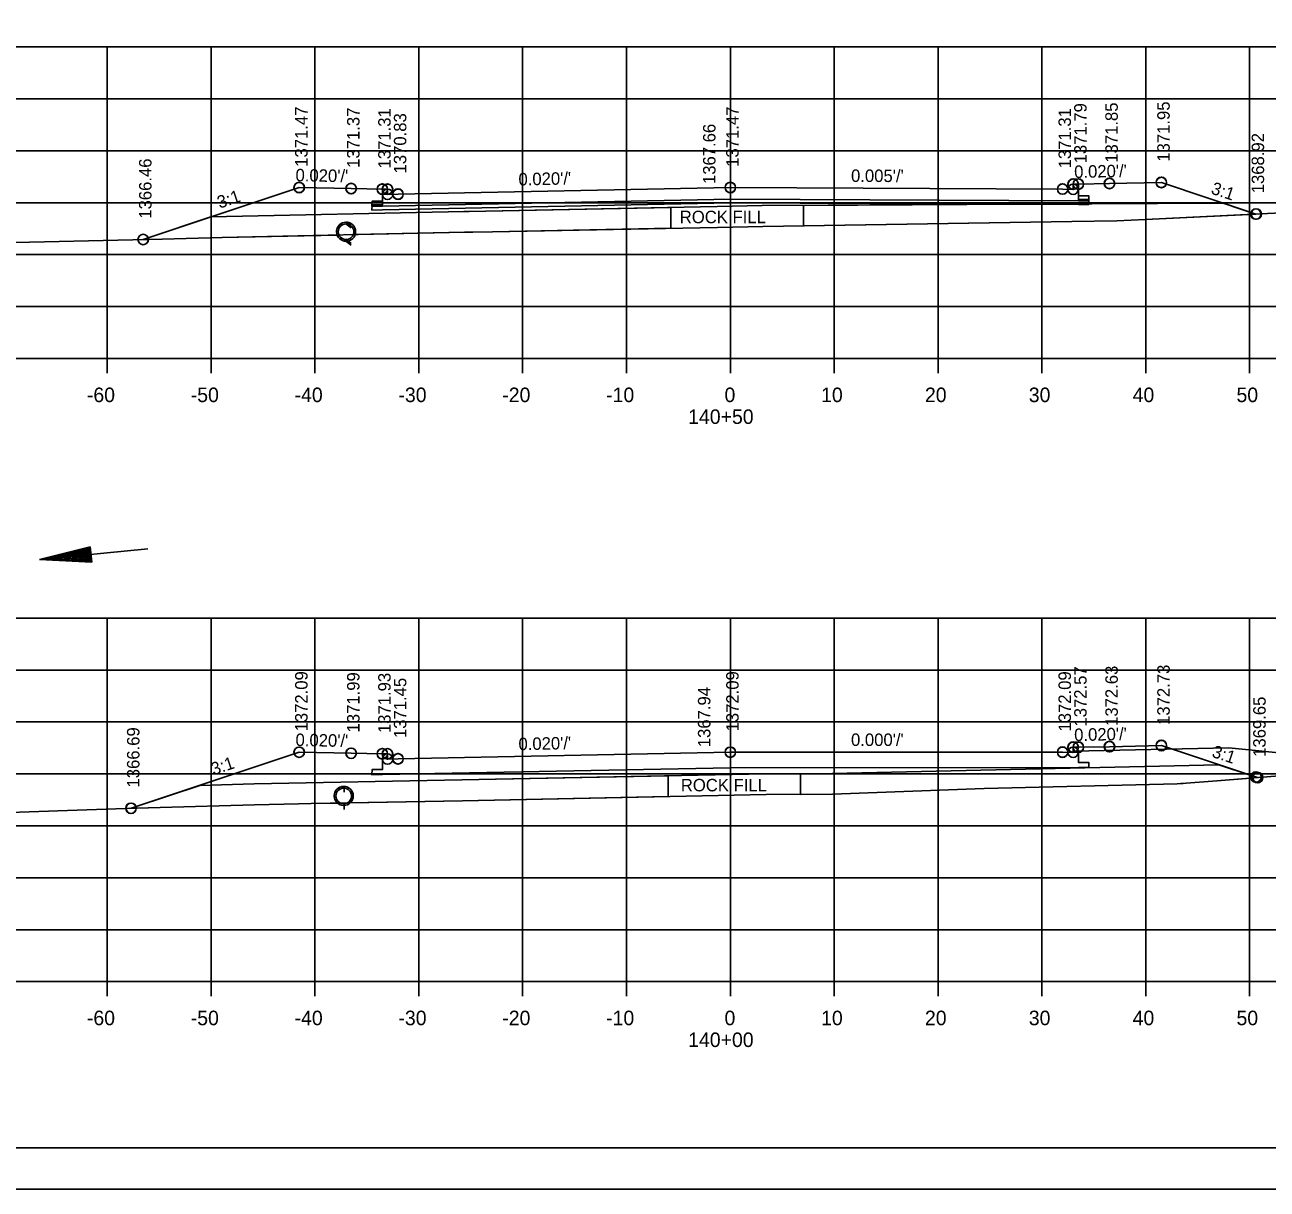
# Model space of a CAD drawing. Extents: x 1374311 to 1383814, y 384102 to 406278.
# Drawn here: x 1381560.7 to 1381680.4, y 389231.4 to 389343.5 of the extents above; entities that cross this region are included whole.
import ezdxf

# ---------------------------------------------------------------- set-up
doc = ezdxf.new("R2010")
doc.units = 0
for name, color, linetype in [('R_Axis', 7, 'Continuous'), ('R_Axis Annot', 7, 'Continuous'), ('R_Border', 7, 'Continuous'), ('R_Draft', 7, 'Continuous'), ('R_Exist Surface', 7, 'Continuous'), ('R_Fin Surface', 7, 'Continuous'), ('R_Grid', 7, 'Continuous'), ('R_No Plot', 7, 'Continuous'), ('R_Water', 7, 'Continuous'), ('R_Xsect Elev', 7, 'Continuous'), ('R_Xsect Slope', 7, 'Continuous')]:
    doc.layers.add(name, color=color, linetype=linetype)

msp = doc.modelspace()

# ---------------------------------------------------------------- linework, layer by layer
at = {"layer": 'R_Axis'}
for p, q in [((1381488.66, 389311.36), (1381768.66, 389311.36)), ((1381568.66, 389309.96), (1381568.66, 389311.36)), ((1381578.66, 389309.96), (1381578.66, 389311.36)), ((1381588.66, 389309.96), (1381588.66, 389311.36)), ((1381598.66, 389309.96), (1381598.66, 389311.36)), ((1381608.66, 389309.96), (1381608.66, 389311.36)), ((1381618.66, 389309.96), (1381618.66, 389311.36)), ((1381628.66, 389309.96), (1381628.66, 389311.36)), ((1381638.66, 389309.96), (1381638.66, 389311.36)), ((1381648.66, 389309.96), (1381648.66, 389311.36)), ((1381658.66, 389309.96), (1381658.66, 389311.36)), ((1381668.66, 389309.96), (1381668.66, 389311.36)), ((1381678.66, 389309.96), (1381678.66, 389311.36)), ((1381488.66, 389251.36), (1381768.66, 389251.36)), ((1381568.66, 389249.96), (1381568.66, 389251.36)), ((1381578.66, 389249.96), (1381578.66, 389251.36)), ((1381588.66, 389249.96), (1381588.66, 389251.36)), ((1381598.66, 389249.96), (1381598.66, 389251.36)), ((1381608.66, 389249.96), (1381608.66, 389251.36)), ((1381618.66, 389249.96), (1381618.66, 389251.36)), ((1381628.66, 389249.96), (1381628.66, 389251.36)), ((1381638.66, 389249.96), (1381638.66, 389251.36)), ((1381648.66, 389249.96), (1381648.66, 389251.36)), ((1381658.66, 389249.96), (1381658.66, 389251.36)), ((1381668.66, 389249.96), (1381668.66, 389251.36)), ((1381678.66, 389249.96), (1381678.66, 389251.36))]:
    msp.add_line(p, q, dxfattribs=at)
at = {"layer": 'R_Border'}
msp.add_line((1381786.84, 389235.36), (1381470.66, 389235.36), dxfattribs=at)
at = {"layer": 'R_Draft'}
for p, q in [((1381567.02, 389293.24), (1381562.12, 389292)), ((1381567.03, 389293.11), (1381562.95, 389292.08)), ((1381567.02, 389293.24), (1381567.17, 389291.74)), ((1381567.17, 389291.74), (1381562.12, 389292)), ((1381567.16, 389291.87), (1381562.95, 389292.08)), ((1381567.05, 389292.98), (1381563.81, 389292.16)), ((1381567.15, 389291.99), (1381563.81, 389292.16)), ((1381567.06, 389292.86), (1381564.64, 389292.25)), ((1381567.13, 389292.12), (1381564.64, 389292.25)), ((1381567.07, 389292.73), (1381565.48, 389292.33)), ((1381567.12, 389292.25), (1381565.48, 389292.33)), ((1381567.08, 389292.61), (1381566.31, 389292.41)), ((1381567.11, 389292.37), (1381566.31, 389292.41)), ((1381661.66, 389273.56), (1381676.65, 389273.86)), ((1381676.65, 389273.86), (1381696.57, 389271.87))]:
    msp.add_line(p, q, dxfattribs=at)
at = {"layer": 'R_Exist Surface'}
for p, q in [((1381591.63, 389324.5), (1381592.15, 389324.11)), ((1381591.63, 389322.67), (1381592.15, 389322.28)), ((1381591.46, 389270.16), (1381591.46, 389269.76)), ((1381591.46, 389268.32), (1381591.46, 389267.93))]:
    msp.add_line(p, q, dxfattribs=at)
for points in [[(1381488.66, 389321.48), (1381496.89, 389321.62), (1381498.05, 389321.64), (1381512.37, 389321.88), (1381515.13, 389321.94), (1381526.33, 389322.13), (1381531.42, 389322.19), (1381541.07, 389322.34), (1381549.06, 389322.42), (1381558.32, 389322.5), (1381573.96, 389322.86), (1381579.74, 389323.01), (1381603.06, 389323.52), (1381603.56, 389323.53), (1381603.85, 389323.54), (1381605.77, 389323.57), (1381627.42, 389323.99), (1381631.78, 389324.08), (1381661.54, 389324.55), (1381665.88, 389324.62), (1381668.65, 389324.75), (1381690.85, 389325.85)], [(1381556.47, 389267.54), (1381570.42, 389268.03), (1381573.75, 389268.14), (1381582.84, 389268.39), (1381587.07, 389268.48), (1381588.3, 389268.5), (1381602.86, 389268.78), (1381632.1, 389269.37), (1381638.51, 389269.4), (1381653.09, 389269.94), (1381671.69, 389270.41), (1381672.03, 389270.42), (1381672.28, 389270.44), (1381672.54, 389270.46), (1381675.08, 389270.65), (1381689.96, 389271.85)]]:
    msp.add_lwpolyline(points, dxfattribs=at)
for centre in [(1381591.66, 389323.57), (1381591.43, 389269.24)]:
    msp.add_circle(centre, 0.917, dxfattribs=at)
at = {"layer": 'R_Fin Surface'}
for p, q in [((1381622.94, 389325.9), (1381622.94, 389323.9)), ((1381622.94, 389323.9), (1381622.94, 389325.9)), ((1381656.66, 389326.21), (1381635.69, 389326.1)), ((1381635.69, 389326.1), (1381635.69, 389324.14)), ((1381635.69, 389326.1), (1381635.69, 389324.14)), ((1381676.14, 389326.31), (1381663.17, 389326.24)), ((1381679.26, 389325.27), (1381676.14, 389326.31)), ((1381578.64, 389324.99), (1381572.6, 389322.98)), ((1381635.69, 389324.14), (1381661.54, 389324.55)), ((1381579.74, 389323.01), (1381590.8, 389323.25)), ((1381603.56, 389323.53), (1381603.85, 389323.54)), ((1381678.8, 389271.21), (1381675.69, 389272.24)), ((1381622.66, 389271.18), (1381622.66, 389269.18)), ((1381622.66, 389269.18), (1381622.66, 389271.18)), ((1381635.42, 389271.38), (1381635.42, 389269.38)), ((1381635.42, 389271.38), (1381635.42, 389269.38)), ((1381577.56, 389270.25), (1381571.43, 389268.21)), ((1381591.46, 389270.16), (1381591.46, 389270.15))]:
    msp.add_line(p, q, dxfattribs=at)
for points in [[(1381572.12, 389322.82), (1381587.15, 389327.82), (1381592.15, 389327.72), (1381595.15, 389327.66), (1381595.65, 389327.66), (1381595.66, 389327.16), (1381596.66, 389327.18), (1381628.66, 389327.82), (1381660.66, 389327.67), (1381661.66, 389327.65), (1381661.67, 389328.15), (1381662.17, 389328.15), (1381665.17, 389328.21), (1381670.17, 389328.31), (1381679.26, 389325.27)], [(1381662.17, 389327.8), (1381662.18, 389326.67), (1381663.18, 389326.68), (1381663.17, 389326.18), (1381662.17, 389326.18), (1381628.66, 389326.34), (1381595.15, 389325.67), (1381594.15, 389325.65), (1381594.16, 389326.15), (1381595.16, 389326.15), (1381595.15, 389327.3)], [(1381578.64, 389324.99), (1381603.01, 389325.52), (1381603.52, 389325.53), (1381627.38, 389325.99), (1381631.74, 389326.08), (1381676.14, 389326.31)], [(1381622.94, 389325.9), (1381603.52, 389325.53), (1381603.01, 389325.52), (1381578.64, 389324.99)], [(1381663.17, 389326.24), (1381663.17, 389326.18), (1381662.17, 389326.18), (1381656.66, 389326.21)], [(1381578.64, 389324.99), (1381578.64, 389324.99)], [(1381661.54, 389324.55), (1381665.88, 389324.62), (1381668.65, 389324.75), (1381679.26, 389325.27)], [(1381572.63, 389322.83), (1381573.96, 389322.86), (1381579.74, 389323.01)], [(1381592.53, 389323.29), (1381603.06, 389323.52), (1381603.56, 389323.53)], [(1381603.85, 389323.54), (1381605.77, 389323.57), (1381622.94, 389323.9)], [(1381570.96, 389268.05), (1381587.15, 389273.45), (1381592.15, 389273.35), (1381595.15, 389273.29), (1381595.65, 389273.29), (1381595.66, 389272.79), (1381596.66, 389272.81), (1381628.66, 389273.45), (1381660.66, 389273.44), (1381661.66, 389273.42), (1381661.67, 389273.92), (1381662.17, 389273.92), (1381665.17, 389273.98), (1381670.17, 389274.08), (1381679.41, 389271)], [(1381662.17, 389273.58), (1381662.18, 389272.46), (1381663.18, 389272.47), (1381663.17, 389271.97), (1381662.17, 389271.97), (1381628.66, 389271.96), (1381595.15, 389271.29), (1381594.15, 389271.27), (1381594.16, 389271.77), (1381595.16, 389271.78), (1381595.15, 389272.93)], [(1381577.56, 389270.25), (1381582.8, 389270.39), (1381602.82, 389270.78), (1381632.08, 389271.37), (1381638.46, 389271.4), (1381675.69, 389272.24)], [(1381675.69, 389272.24), (1381638.46, 389271.4), (1381635.42, 389271.38)], [(1381622.66, 389271.18), (1381602.82, 389270.78), (1381582.8, 389270.39), (1381577.56, 389270.25)], [(1381635.42, 389269.38), (1381638.51, 389269.4), (1381653.09, 389269.94), (1381671.69, 389270.41), (1381672.03, 389270.42), (1381672.28, 389270.44), (1381672.54, 389270.46), (1381675.08, 389270.65), (1381678.79, 389270.95)], [(1381591.46, 389270.15), (1381591.46, 389270.16)], [(1381592.06, 389268.57), (1381602.86, 389268.78), (1381622.66, 389269.18)], [(1381571.46, 389268.07), (1381573.75, 389268.14), (1381582.84, 389268.39), (1381587.07, 389268.48), (1381588.3, 389268.5), (1381590.82, 389268.55)]]:
    msp.add_lwpolyline(points, dxfattribs=at)
for centre, radius, start, end in [((1381591.66, 389323.57), 0.917, 342.002, 200.4907), ((1381572.13, 389322.82), 0.5, 0.7175, 18.2132), ((1381679.27, 389271.06), 0.5, 163.0446, 192.7009), ((1381591.43, 389269.24), 0.917, 88.1857, 228.6165), ((1381591.43, 389269.24), 0.917, 313.598, 88.1796), ((1381570.96, 389268.05), 0.5, 1.9076, 18.4349)]:
    msp.add_arc(centre, radius, start, end, dxfattribs=at)
at = {"layer": 'R_Grid'}
for p, q in [((1381488.66, 389341.36), (1381768.66, 389341.36)), ((1381568.66, 389311.36), (1381568.66, 389341.36)), ((1381578.66, 389311.36), (1381578.66, 389341.36)), ((1381588.66, 389311.36), (1381588.66, 389341.36)), ((1381598.66, 389311.36), (1381598.66, 389341.36)), ((1381608.66, 389311.36), (1381608.66, 389341.36)), ((1381618.66, 389311.36), (1381618.66, 389341.36)), ((1381628.66, 389311.36), (1381628.66, 389341.36)), ((1381638.66, 389311.36), (1381638.66, 389341.36)), ((1381648.66, 389311.36), (1381648.66, 389341.36)), ((1381658.66, 389311.36), (1381658.66, 389341.36)), ((1381668.66, 389311.36), (1381668.66, 389341.36)), ((1381678.66, 389311.36), (1381678.66, 389341.36)), ((1381488.66, 389336.36), (1381768.66, 389336.36)), ((1381488.66, 389331.36), (1381768.66, 389331.36)), ((1381488.66, 389326.36), (1381768.66, 389326.36)), ((1381488.66, 389321.36), (1381768.66, 389321.36)), ((1381488.66, 389316.36), (1381768.66, 389316.36)), ((1381488.66, 389311.36), (1381768.66, 389311.36)), ((1381488.66, 389286.36), (1381768.66, 389286.36)), ((1381568.66, 389251.36), (1381568.66, 389286.36)), ((1381578.66, 389251.36), (1381578.66, 389286.36)), ((1381588.66, 389251.36), (1381588.66, 389286.36)), ((1381598.66, 389251.36), (1381598.66, 389286.36)), ((1381608.66, 389251.36), (1381608.66, 389286.36)), ((1381618.66, 389251.36), (1381618.66, 389286.36)), ((1381628.66, 389251.36), (1381628.66, 389286.36)), ((1381638.66, 389251.36), (1381638.66, 389286.36)), ((1381648.66, 389251.36), (1381648.66, 389286.36)), ((1381658.66, 389251.36), (1381658.66, 389286.36)), ((1381668.66, 389251.36), (1381668.66, 389286.36)), ((1381678.66, 389251.36), (1381678.66, 389286.36)), ((1381488.66, 389281.36), (1381768.66, 389281.36)), ((1381488.66, 389276.36), (1381768.66, 389276.36)), ((1381488.66, 389271.36), (1381768.66, 389271.36)), ((1381488.66, 389266.36), (1381768.66, 389266.36)), ((1381488.66, 389261.36), (1381768.66, 389261.36)), ((1381488.66, 389256.36), (1381768.66, 389256.36)), ((1381488.66, 389251.36), (1381768.66, 389251.36))]:
    msp.add_line(p, q, dxfattribs=at)
at = {"layer": 'R_No Plot'}
msp.add_line((1381458.26, 389231.38), (1381791.59, 389231.38), dxfattribs=at)
for points in [[(1381458.25, 389444.71), (1381791.59, 389444.71), (1381791.59, 389231.37), (1381458.25, 389231.37)], [(1381704.58, 389440.82), (1381704.58, 389430.94), (1381740.31, 389430.94), (1381740.31, 389428.02), (1381763.51, 389428.02), (1381763.51, 389404.8), (1381786.84, 389404.8), (1381786.84, 389235.36), (1381470.66, 389235.36), (1381470.66, 389440.82)], [(1381572.12, 389322.82), (1381573.96, 389322.86), (1381579.74, 389323.01), (1381603.06, 389323.52), (1381603.56, 389323.53), (1381603.85, 389323.54), (1381605.77, 389323.57), (1381627.42, 389323.99), (1381631.78, 389324.08), (1381661.54, 389324.55), (1381665.88, 389324.62), (1381668.65, 389324.75), (1381679.26, 389325.27), (1381670.17, 389328.31), (1381665.17, 389328.21), (1381662.17, 389328.15), (1381662.18, 389327.03), (1381663.18, 389327.04), (1381663.17, 389326.54), (1381662.17, 389326.54), (1381628.66, 389326.7), (1381595.15, 389326.03), (1381594.15, 389326.01), (1381594.16, 389326.51), (1381595.16, 389326.51), (1381595.15, 389327.66), (1381592.15, 389327.72), (1381587.15, 389327.82)]]:
    msp.add_lwpolyline(points, close=True, dxfattribs=at)
for centre in [(1381587.14, 389327.83), (1381587.15, 389327.83), (1381587.15, 389327.82), (1381592.14, 389327.73), (1381592.15, 389327.73), (1381592.15, 389327.72), (1381595.14, 389327.67), (1381595.15, 389327.67), (1381595.15, 389327.66), (1381595.64, 389327.67), (1381595.65, 389327.67), (1381595.65, 389327.66), (1381596.65, 389327.19), (1381596.66, 389327.19), (1381596.66, 389327.18), (1381628.65, 389327.83), (1381628.66, 389327.83), (1381628.66, 389327.82), (1381660.65, 389327.68), (1381660.66, 389327.68), (1381660.66, 389327.67), (1381661.66, 389328.16), (1381661.66, 389327.66), (1381661.67, 389328.16), (1381661.67, 389328.15), (1381662.16, 389328.16), (1381662.17, 389328.16), (1381662.17, 389328.15), (1381665.16, 389328.22), (1381665.17, 389328.22), (1381665.17, 389328.21), (1381670.16, 389328.32), (1381670.17, 389328.32), (1381670.17, 389328.31), (1381595.66, 389327.17), (1381679.26, 389325.27), (1381679.29, 389325.28), (1381679.3, 389325.27), (1381572.12, 389322.82), (1381572.12, 389322.82), (1381572.12, 389322.82), (1381572.12, 389322.82), (1381572.13, 389322.82), (1381572.13, 389322.82), (1381587.14, 389273.45), (1381587.15, 389273.45), (1381587.15, 389273.45), (1381592.14, 389273.35), (1381592.15, 389273.35), (1381592.15, 389273.35), (1381628.65, 389273.45), (1381628.66, 389273.45), (1381628.66, 389273.45), (1381660.65, 389273.46), (1381660.66, 389273.46), (1381660.66, 389273.44), (1381661.66, 389273.94), (1381661.66, 389273.44), (1381661.67, 389273.94), (1381661.67, 389273.92), (1381662.16, 389273.94), (1381662.17, 389273.94), (1381662.17, 389273.92), (1381665.16, 389274), (1381665.17, 389274), (1381665.17, 389273.98), (1381670.16, 389274.1), (1381670.17, 389274.1), (1381670.17, 389274.08), (1381595.14, 389273.29), (1381595.15, 389273.29), (1381595.15, 389273.29), (1381595.64, 389273.29), (1381595.65, 389273.29), (1381595.65, 389273.29), (1381595.66, 389272.79), (1381596.65, 389272.81), (1381596.66, 389272.81), (1381596.66, 389272.81), (1381679.27, 389271.06), (1381679.41, 389271), (1381679.45, 389271.01), (1381570.94, 389268.05), (1381570.94, 389268.05), (1381570.96, 389268.05), (1381570.96, 389268.05), (1381570.96, 389268.05), (1381570.96, 389268.05)]:
    msp.add_circle(centre, 0.5, dxfattribs=at)
at = {"layer": 'R_Water'}
for p, q in [((1381591.63, 389324.34), (1381592.15, 389323.95)), ((1381591.63, 389322.84), (1381592.15, 389322.45)), ((1381572.57, 389293.03), (1381562.12, 389292)), ((1381591.46, 389269.99), (1381591.46, 389269.6)), ((1381591.46, 389268.49), (1381591.46, 389268.1))]:
    msp.add_line(p, q, dxfattribs=at)
for centre in [(1381591.66, 389323.57), (1381591.43, 389269.24)]:
    msp.add_circle(centre, 0.75, dxfattribs=at)

# ---------------------------------------------------------------- texts
at = {"layer": 'R_Axis Annot'}
for s, p in [('-60', (1381566.7, 389307.16)), ('-50', (1381576.7, 389307.16)), ('-40', (1381586.7, 389307.16)), ('-30', (1381596.7, 389307.16)), ('-20', (1381606.7, 389307.16)), ('-10', (1381616.7, 389307.16)), ('0', (1381628.1, 389307.16)), ('10', (1381637.4, 389307.16)), ('20', (1381647.4, 389307.16)), ('30', (1381657.4, 389307.16)), ('40', (1381667.4, 389307.16)), ('50', (1381677.4, 389307.16)), ('140+50', (1381624.6, 389305.06)), ('-60', (1381566.7, 389247.16)), ('-50', (1381576.7, 389247.16)), ('-40', (1381586.7, 389247.16)), ('-30', (1381596.7, 389247.16)), ('-20', (1381606.7, 389247.16)), ('-10', (1381616.7, 389247.16)), ('0', (1381628.1, 389247.16)), ('10', (1381637.4, 389247.16)), ('20', (1381647.4, 389247.16)), ('30', (1381657.4, 389247.16)), ('40', (1381667.4, 389247.16)), ('50', (1381677.4, 389247.16)), ('140+00', (1381624.6, 389245.06))]:
    msp.add_text(s, height=1.4, dxfattribs=at).set_placement(p)
at = {"layer": 'R_Fin Surface'}
for p in [(1381623.79, 389324.39), (1381623.89, 389269.68)]:
    msp.add_text('ROCK FILL', height=1.2, dxfattribs=at).set_placement(p)
at = {"layer": 'R_Xsect Elev'}
for s, p in [('1371.47', (1381587.95, 389329.82)), ('1371.37', (1381592.95, 389329.72)), ('1371.31', (1381595.95, 389329.66)), ('1370.83', (1381597.46, 389329.18)), ('1371.47', (1381629.46, 389329.82)), ('1371.31', (1381661.46, 389329.67)), ('1371.79', (1381662.97, 389330.15)), ('1371.85', (1381665.97, 389330.21)), ('1371.95', (1381670.97, 389330.31)), ('1367.66', (1381627.23, 389328.16)), ('1368.92', (1381680.06, 389327.27)), ('1366.46', (1381572.92, 389324.82)), ('1372.09', (1381587.95, 389275.45)), ('1371.99', (1381592.95, 389275.35)), ('1372.09', (1381629.46, 389275.45)), ('1372.09', (1381661.46, 389275.44)), ('1372.57', (1381662.97, 389275.92)), ('1372.63', (1381665.97, 389275.98)), ('1372.73', (1381670.97, 389276.08)), ('1371.93', (1381595.95, 389275.29)), ('1371.45', (1381597.46, 389274.81)), ('1367.94', (1381626.74, 389273.93)), ('1369.65', (1381680.21, 389273)), ('1366.69', (1381571.76, 389270.05))]:
    msp.add_text(s, height=1.2, rotation=90, dxfattribs=at).set_placement(p)
at = {"layer": 'R_Xsect Slope'}
for s, rotation, p in [("0.020'/'", 1.1458, (1381661.78, 389328.74)), ("0.020'/'", 358.8542, (1381586.78, 389328.43)), ("0.020'/'", 1.1458, (1381608.27, 389328.02)), ("0.005'/'", 359.7151, (1381640.28, 389328.37)), ('3:1', 341.5651, (1381674.87, 389327.26)), ('3:1', 18.4349, (1381579.48, 389325.79)), ("0.020'/'", 358.8542, (1381586.78, 389274.05)), ("0.000'/'", 359.9952, (1381640.28, 389274.05)), ("0.020'/'", 1.1458, (1381661.78, 389274.52)), ("0.020'/'", 1.1458, (1381608.27, 389273.64)), ('3:1', 341.5651, (1381674.95, 389273.02)), ('3:1', 18.4349, (1381578.89, 389271.22))]:
    msp.add_text(s, height=1.2, rotation=rotation, dxfattribs=at).set_placement(p)

doc.saveas('drawing.dxf')
